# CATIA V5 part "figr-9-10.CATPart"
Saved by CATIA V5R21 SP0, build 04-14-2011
Part number: Part1
Bounding box of the stored display mesh (mm): x -15.705 to 98.193, y 0 to 272.268, z -20.723 to 20.723
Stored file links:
  D:\CATIA V5R21 E-RESOURCES\CATIA-V5R21\catia-v5r21-prt\c09-catia-v5r20-prt\c09-catia-v5r21-figr-9-10.CATPart
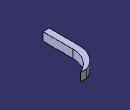
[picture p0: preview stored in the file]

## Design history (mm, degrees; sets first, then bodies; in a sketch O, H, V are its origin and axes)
Body1 (main body)
  Sketch1 on xy-plane, origin (0, 0, 0), H (1, 0, 0), V (0, 1, 0)
    line L1 (0, 0) -> (0, 150)
    arc A1 centre (131.8599, 150) radius 131.8599 from (0, 150) to (82.4884, 272.2681) cw
    length L1 = 150
    tangency: A1 L1
  Sketch2 on zx-plane, origin (0, 0, 0), H (-1, 0, 0), V (0, 0, 1)
    line L1 (15.7048, 20.7231) -> (15.7048, -20.7231)
    line L2 (15.7048, -20.7231) -> (-15.7048, -20.7231)
    line L3 (-15.7048, -20.7231) -> (-15.7048, 20.7231)
    line L4 (-15.7048, 20.7231) -> (15.7048, 20.7231)
    vertical: L1 V, L3 V
    horizontal: L2 H, L4 H
    equidistance: L1 L3 O, L2 L4 O
  Rib1: profile Sketch2, centre curve Sketch1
